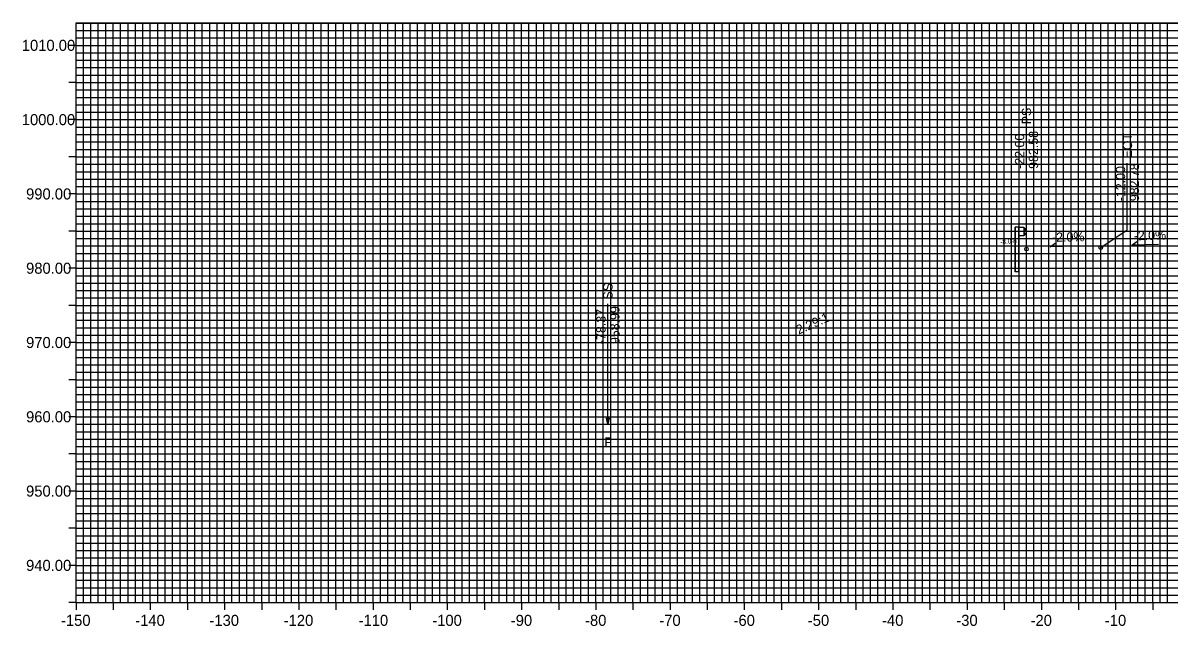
# Model space of a CAD drawing. Extents: x -157 to 157, y 932 to 1013.
# Drawn here: x -157.2 to -2.8, y 931.8 to 1013 of the extents above; entities that cross this region are included whole.
import ezdxf

# ---------------------------------------------------------------- set-up
doc = ezdxf.new("R2010")
doc.units = 0
for name, color, linetype in [('E_NCDOT_Terrain_Model_Breakline', 7, 'Continuous'), ('E_NCDOT_Terrain_Model_Contour_Imported', 7, 'Continuous'), ('E_NCDOT_Terrain_Model_Contour_Major', 7, 'Continuous'), ('E_NCDOT_Terrain_Model_Contour_Minor', 7, 'Continuous'), ('E_NCDOT_Terrain_Model_Flow_Arrows', 7, 'Continuous'), ('E_NCDOT_Terrain_Model_Hole', 7, 'Continuous'), ('E_NCDOT_Terrain_Model_Island', 7, 'Continuous'), ('E_NCDOT_Terrain_Model_Points_High', 7, 'Continuous'), ('E_NCDOT_Terrain_Model_Points_Low', 7, 'Continuous'), ('E_NCDOT_Terrain_Model_Triangles', 7, 'Continuous'), ('E_NCDOT_Vertical_Profile_Ground_Line', 7, 'Continuous'), ('P_HYD_Contour_Major', 7, 'Continuous'), ('P_HYD_Contour_Minor', 7, 'Continuous'), ('P_HYD_TC_Surface_Grass', 7, 'Continuous')]:
    doc.layers.add(name, color=color, linetype=linetype)

msp = doc.modelspace()

# ---------------------------------------------------------------- linework, layer by layer
at = {"layer": 'E_NCDOT_Terrain_Model_Breakline'}
for p, q in [((-150, 1013), (150, 1013)), ((-149, 935), (-149, 1013.02)), ((-148, 935), (-148, 1013.02)), ((-147, 935), (-147, 1013.02)), ((-146, 935), (-146, 1013.02)), ((-144, 935), (-144, 1013.02)), ((-143, 935), (-143, 1013.02)), ((-142, 935), (-142, 1013.02)), ((-141, 935), (-141, 1013.02)), ((-139, 935), (-139, 1013.02)), ((-138, 935), (-138, 1013.02)), ((-137, 935), (-137, 1013.02)), ((-136, 935), (-136, 1013.02)), ((-134, 935), (-134, 1013.02)), ((-133, 935), (-133, 1013.02)), ((-132, 935), (-132, 1013.02)), ((-131, 935), (-131, 1013.02)), ((-129, 935), (-129, 1013.02)), ((-128, 935), (-128, 1013.02)), ((-127, 935), (-127, 1013.02)), ((-126, 935), (-126, 1013.02)), ((-124, 935), (-124, 1013.02)), ((-123, 935), (-123, 1013.02)), ((-122, 935), (-122, 1013.02)), ((-121, 935), (-121, 1013.02)), ((-119, 935), (-119, 1013.02)), ((-118, 935), (-118, 1013.02)), ((-117, 935), (-117, 1013.02)), ((-116, 935), (-116, 1013.02)), ((-114, 935), (-114, 1013.02)), ((-113, 935), (-113, 1013.02)), ((-112, 935), (-112, 1013.02)), ((-111, 935), (-111, 1013.02)), ((-109, 935), (-109, 1013.02)), ((-108, 935), (-108, 1013.02)), ((-107, 935), (-107, 1013.02)), ((-106, 935), (-106, 1013.02)), ((-104, 935), (-104, 1013.02)), ((-103, 935), (-103, 1013.02)), ((-102, 935), (-102, 1013.02)), ((-101, 935), (-101, 1013.02)), ((-99, 935), (-99, 1013.02)), ((-98, 935), (-98, 1013.02)), ((-97, 935), (-97, 1013.02)), ((-96, 935), (-96, 1013.02)), ((-94, 935), (-94, 1013.02)), ((-93, 935), (-93, 1013.02)), ((-92, 935), (-92, 1013.02)), ((-91, 935), (-91, 1013.02)), ((-89, 935), (-89, 1013.02)), ((-88, 935), (-88, 1013.02)), ((-87, 935), (-87, 1013.02)), ((-86, 935), (-86, 1013.02)), ((-84, 935), (-84, 1013.02)), ((-83, 935), (-83, 1013.02)), ((-82, 935), (-82, 1013.02)), ((-81, 935), (-81, 1013.02)), ((-79, 935), (-79, 1013.02)), ((-78, 935), (-78, 1013.02)), ((-77, 935), (-77, 1013.02)), ((-76, 935), (-76, 1013.02)), ((-74, 935), (-74, 1013.02)), ((-73, 935), (-73, 1013.02)), ((-72, 935), (-72, 1013.02)), ((-71, 935), (-71, 1013.02)), ((-69, 935), (-69, 1013.02)), ((-68, 935), (-68, 1013.02)), ((-67, 935), (-67, 1013.02)), ((-66, 935), (-66, 1013.02)), ((-64, 935), (-64, 1013.02)), ((-63, 935), (-63, 1013.02)), ((-62, 935), (-62, 1013.02)), ((-61, 935), (-61, 1013.02)), ((-59, 935), (-59, 1013.02)), ((-58, 935), (-58, 1013.02)), ((-57, 935), (-57, 1013.02)), ((-56, 935), (-56, 1013.02)), ((-54, 935), (-54, 1013.02)), ((-53, 935), (-53, 1013.02)), ((-52, 935), (-52, 1013.02)), ((-51, 935), (-51, 1013.02)), ((-49, 935), (-49, 1013.02)), ((-48, 935), (-48, 1013.02)), ((-47, 935), (-47, 1013.02)), ((-46, 935), (-46, 1013.02)), ((-44, 935), (-44, 1013.02)), ((-43, 935), (-43, 1013.02)), ((-42, 935), (-42, 1013.02)), ((-41, 935), (-41, 1013.02)), ((-39, 935), (-39, 1013.02)), ((-38, 935), (-38, 1013.02)), ((-37, 935), (-37, 1013.02)), ((-36, 935), (-36, 1013.02)), ((-34, 935), (-34, 1013.02)), ((-33, 935), (-33, 1013.02)), ((-32, 935), (-32, 1013.02)), ((-31, 935), (-31, 1013.02)), ((-29, 935), (-29, 1013.02)), ((-28, 935), (-28, 1013.02)), ((-27, 935), (-27, 1013.02)), ((-26, 935), (-26, 1013.02)), ((-24, 935), (-24, 1013.02)), ((-23, 935), (-23, 1013.02)), ((-22, 935), (-22, 1013.02)), ((-21, 935), (-21, 1013.02)), ((-19, 935), (-19, 1013.02)), ((-18, 935), (-18, 1013.02)), ((-17, 935), (-17, 1013.02)), ((-16, 935), (-16, 1013.02)), ((-14, 935), (-14, 1013.02)), ((-13, 935), (-13, 1013.02)), ((-12, 935), (-12, 1013.02)), ((-11, 935), (-11, 1013.02)), ((-9, 935), (-9, 1013.02)), ((-8, 935), (-8, 1013.02)), ((-7, 935), (-7, 1013.02)), ((-6, 935), (-6, 1013.02)), ((-4, 935), (-4, 1013.02)), ((-3, 935), (-3, 1013.02)), ((-150, 1012), (150, 1012)), ((-150, 1011), (150, 1011)), ((-150, 1009), (150, 1009)), ((-150, 1008), (150, 1008)), ((-150, 1007), (150, 1007)), ((-150, 1006), (150, 1006)), ((-150, 1004), (150, 1004)), ((-150, 1003), (150, 1003)), ((-150, 1002), (150, 1002)), ((-150, 1001), (150, 1001)), ((-150, 999), (150, 999)), ((-150, 998), (150, 998)), ((-150, 997), (150, 997)), ((-150, 996), (150, 996)), ((-150, 994), (150, 994)), ((-150, 993), (150, 993)), ((-150, 992), (150, 992)), ((-150, 991), (150, 991)), ((-150, 989), (150, 989)), ((-150, 988), (150, 988)), ((-150, 987), (150, 987)), ((-150, 986), (150, 986)), ((-150, 984), (150, 984)), ((-150, 983), (150, 983)), ((-150, 982), (150, 982)), ((-150, 981), (150, 981)), ((-150, 979), (150, 979)), ((-150, 978), (150, 978)), ((-150, 977), (150, 977)), ((-150, 976), (150, 976)), ((-150, 974), (150, 974)), ((-150, 973), (150, 973)), ((-150, 972), (150, 972)), ((-150, 971), (150, 971)), ((-150, 969), (150, 969)), ((-150, 968), (150, 968)), ((-150, 967), (150, 967)), ((-150, 966), (150, 966)), ((-150, 964), (150, 964)), ((-150, 963), (150, 963)), ((-150, 962), (150, 962)), ((-150, 961), (150, 961)), ((-150, 959), (150, 959)), ((-150, 958), (150, 958)), ((-150, 957), (150, 957)), ((-150, 956), (150, 956)), ((-150, 954), (150, 954)), ((-150, 953), (150, 953)), ((-150, 952), (150, 952)), ((-150, 951), (150, 951)), ((-150, 949), (150, 949)), ((-150, 948), (150, 948)), ((-150, 947), (150, 947)), ((-150, 946), (150, 946)), ((-150, 944), (150, 944)), ((-150, 943), (150, 943)), ((-150, 942), (150, 942)), ((-150, 941), (150, 941)), ((-150, 939), (150, 939)), ((-150, 938), (150, 938)), ((-150, 937), (150, 937)), ((-150, 936), (150, 936))]:
    msp.add_line(p, q, dxfattribs=at)
at = {"layer": 'E_NCDOT_Terrain_Model_Contour_Imported'}
for p, q in [((-18.8, 982.88), (-18.12, 983.38)), ((-7.8, 983.1), (-7.12, 983.6)), ((-15.2, 982.96), (-18.8, 982.88)), ((-4.2, 983.18), (-7.8, 983.1))]:
    msp.add_line(p, q, dxfattribs=at)
at = {"layer": 'E_NCDOT_Terrain_Model_Contour_Minor'}
for p, q in [((-8.44, 985.17), (-8.44, 994.13)), ((-12, 982.78), (-8.44, 985.17))]:
    msp.add_line(p, q, dxfattribs=at)
at = {"layer": 'E_NCDOT_Terrain_Model_Hole'}
for p, q in [((-140, 935), (-140, 1013.02)), ((-130, 935), (-130, 1013.02)), ((-120, 935), (-120, 1013.02)), ((-110, 935), (-110, 1013.02)), ((-100, 935), (-100, 1013.02)), ((-90, 935), (-90, 1013.02)), ((-80, 935), (-80, 1013.02)), ((-70, 935), (-70, 1013.02)), ((-60, 935), (-60, 1013.02)), ((-50, 935), (-50, 1013.02)), ((-40, 935), (-40, 1013.02)), ((-30, 935), (-30, 1013.02)), ((-20, 935), (-20, 1013.02)), ((-10, 935), (-10, 1013.02)), ((-150, 1010), (150, 1010)), ((-150, 1000), (150, 1000)), ((-150, 990), (150, 990)), ((-150, 980), (150, 980)), ((-150, 970), (150, 970)), ((-150, 960), (150, 960)), ((-150, 950), (150, 950)), ((-150, 940), (150, 940))]:
    msp.add_line(p, q, dxfattribs=at)
at = {"layer": 'E_NCDOT_Terrain_Model_Points_High'}
for p, q in [((-145, 935), (-145, 1013.02)), ((-140, 935), (-140, 1013.02)), ((-135, 935), (-135, 1013.02)), ((-130, 935), (-130, 1013.02)), ((-125, 935), (-125, 1013.02)), ((-120, 935), (-120, 1013.02)), ((-115, 935), (-115, 1013.02)), ((-110, 935), (-110, 1013.02)), ((-105, 935), (-105, 1013.02)), ((-100, 935), (-100, 1013.02)), ((-95, 935), (-95, 1013.02)), ((-90, 935), (-90, 1013.02)), ((-85, 935), (-85, 1013.02)), ((-80, 935), (-80, 1013.02)), ((-75, 935), (-75, 1013.02)), ((-70, 935), (-70, 1013.02)), ((-65, 935), (-65, 1013.02)), ((-60, 935), (-60, 1013.02)), ((-55, 935), (-55, 1013.02)), ((-50, 935), (-50, 1013.02)), ((-45, 935), (-45, 1013.02)), ((-40, 935), (-40, 1013.02)), ((-35, 935), (-35, 1013.02)), ((-30, 935), (-30, 1013.02)), ((-25, 935), (-25, 1013.02)), ((-20, 935), (-20, 1013.02)), ((-15, 935), (-15, 1013.02)), ((-10, 935), (-10, 1013.02)), ((-5, 935), (-5, 1013.02)), ((-150, 1010), (-150.96, 1010)), ((-150, 1010), (150, 1010)), ((-150, 1005), (-150.96, 1005)), ((-150, 1005), (150, 1005)), ((-150, 1000), (-150.96, 1000)), ((-150, 1000), (150, 1000)), ((-150, 995), (-150.96, 995)), ((-150, 995), (150, 995)), ((-150, 990), (-150.96, 990)), ((-150, 990), (150, 990)), ((-150, 985), (-150.96, 985)), ((-150, 985), (150, 985)), ((-150, 980), (-150.96, 980)), ((-150, 980), (150, 980)), ((-150, 975), (-150.96, 975)), ((-150, 975), (150, 975)), ((-150, 970), (-150.96, 970)), ((-150, 970), (150, 970)), ((-150, 965), (-150.96, 965)), ((-150, 965), (150, 965)), ((-150, 960), (-150.96, 960)), ((-150, 960), (150, 960)), ((-150, 955), (-150.96, 955)), ((-150, 955), (150, 955)), ((-150, 950), (-150.96, 950)), ((-150, 950), (150, 950)), ((-150, 945), (-150.96, 945)), ((-150, 945), (150, 945)), ((-150, 940), (-150.96, 940)), ((-150, 940), (150, 940)), ((-150, 935), (-150.96, 935)), ((-150, 935), (-150, 934.04)), ((-145, 935), (-145, 934.04)), ((-140, 935), (-140, 934.04)), ((-135, 935), (-135, 934.04)), ((-130, 935), (-130, 934.04)), ((-125, 935), (-125, 934.04)), ((-120, 935), (-120, 934.04)), ((-115, 935), (-115, 934.04)), ((-110, 935), (-110, 934.04)), ((-105, 935), (-105, 934.04)), ((-100, 935), (-100, 934.04)), ((-95, 935), (-95, 934.04)), ((-90, 935), (-90, 934.04)), ((-85, 935), (-85, 934.04)), ((-80, 935), (-80, 934.04)), ((-75, 935), (-75, 934.04)), ((-70, 935), (-70, 934.04)), ((-65, 935), (-65, 934.04)), ((-60, 935), (-60, 934.04)), ((-55, 935), (-55, 934.04)), ((-50, 935), (-50, 934.04)), ((-45, 935), (-45, 934.04)), ((-40, 935), (-40, 934.04)), ((-35, 935), (-35, 934.04)), ((-30, 935), (-30, 934.04)), ((-25, 935), (-25, 934.04)), ((-20, 935), (-20, 934.04)), ((-15, 935), (-15, 934.04)), ((-10, 935), (-10, 934.04)), ((-5, 935), (-5, 934.04))]:
    msp.add_line(p, q, dxfattribs=at)
at = {"layer": 'E_NCDOT_Terrain_Model_Points_Low'}
for p, q in [((-150, 1013.02), (150, 1013.02)), ((-150, 935), (-150, 1013.02)), ((-150, 935), (150, 935))]:
    msp.add_line(p, q, dxfattribs=at)
at = {"layer": 'E_NCDOT_Vertical_Profile_Ground_Line'}
for p, q in [((-22, 982.58), (-22, 998.18)), ((-78.37, 958.99), (-78.37, 975.19))]:
    msp.add_line(p, q, dxfattribs=at)
msp.add_lwpolyline([(-78.37, 958.99), (-78.55, 959.81), (-78.2, 959.81)], close=True, dxfattribs=at)
for centre in [(-22, 982.58), (-12, 982.78)]:
    msp.add_circle(centre, 0.24, dxfattribs=at)
at = {"layer": 'P_HYD_TC_Surface_Grass'}
for p, q in [((-23.03, 985.52), (-23.53, 985.52)), ((-23.53, 985.52), (-23.51, 985.52)), ((-23.53, 979.52), (-23.53, 985.52)), ((-23.51, 985.52), (-23.51, 979.52)), ((-23.04, 985.52), (-23.03, 985.52)), ((-23.04, 979.52), (-23.04, 985.52)), ((-23.03, 985.52), (-22.36, 985.52)), ((-23.03, 985.52), (-23.03, 979.52)), ((-22.36, 985.52), (-22.36, 984.35)), ((-22.36, 985.44), (-22.27, 985.42)), ((-22.36, 984.98), (-22.36, 984.93)), ((-22.36, 984.93), (-22.36, 984.88)), ((-22.12, 985.19), (-22.33, 985.05)), ((-22.33, 984.82), (-22.12, 984.68)), ((-22.26, 985.41), (-22.12, 985.32)), ((-22.36, 984.35), (-23.03, 984.35)), ((-22.27, 984.44), (-22.36, 984.43)), ((-22.12, 984.55), (-22.26, 984.45)), ((-23.03, 979.52), (-23.53, 979.52)), ((-23.51, 979.52), (-23.53, 979.52)), ((-23.03, 979.52), (-23.04, 979.52))]:
    msp.add_line(p, q, dxfattribs=at)
for centre, radius, start, end in [((-22.28, 984.98), 0.0787, 124.6522, 179.98), ((-22.28, 984.88), 0.0787, 180.02, 235.3478), ((-22.27, 985.39), 0.0328, 54.7024, 80), ((-22.16, 985.25), 0.0787, 304.6522, 54.7024), ((-22.27, 984.48), 0.0328, 280, 305.2976), ((-22.16, 984.61), 0.0787, 305.2976, 55.3478)]:
    msp.add_arc(centre, radius, start, end, dxfattribs=at)

# ---------------------------------------------------------------- texts
at = {"layer": 'E_NCDOT_Terrain_Model_Contour_Major'}
for s, p in [('SS', (-77.75, 975.79)), ('-78.37', (-78.69, 969.79)), ('958.99', (-76.81, 969.79))]:
    msp.add_text(s, height=1.248, rotation=90, dxfattribs=at).set_placement(p)
msp.add_text('F', height=1.25, dxfattribs=at).set_placement((-78.85, 955.97))
at = {"layer": 'E_NCDOT_Terrain_Model_Flow_Arrows'}
msp.add_text('-8.0%', height=0.624, rotation=4.5739, dxfattribs=at).set_placement((-25.51, 983.23))
at = {"layer": 'E_NCDOT_Terrain_Model_Island'}
for s, p in [('1010.00', (-157.31, 1009.26)), ('1000.00', (-157.31, 999.26)), ('990.00', (-156.73, 989.26)), ('980.00', (-156.73, 979.26)), ('970.00', (-156.73, 969.26)), ('960.00', (-156.73, 959.26)), ('950.00', (-156.73, 949.26)), ('940.00', (-156.73, 939.26)), ('-150', (-152.03, 931.86)), ('-140', (-142.03, 931.86)), ('-130', (-132.03, 931.86)), ('-120', (-122.03, 931.86)), ('-110', (-111.95, 931.86)), ('-100', (-102.03, 931.86)), ('-90', (-91.45, 931.86)), ('-80', (-81.45, 931.86)), ('-70', (-71.45, 931.86)), ('-60', (-61.45, 931.86)), ('-50', (-51.45, 931.86)), ('-40', (-41.45, 931.86)), ('-30', (-31.45, 931.86)), ('-20', (-21.45, 931.86)), ('-10', (-11.45, 931.86))]:
    msp.add_text(s, height=1.488, dxfattribs=at).set_placement(p)
at = {"layer": 'E_NCDOT_Terrain_Model_Triangles'}
for s, p in [('PS', (-21.38, 999.38)), ('-22.00', (-22.31, 993.38)), ('982.58', (-20.44, 993.38)), ('EOT', (-7.78, 994.78)), ('-12.00', (-8.71, 989.02)), ('982.78', (-6.84, 989.02))]:
    msp.add_text(s, height=1.248, rotation=90, dxfattribs=at).set_placement(p)
at = {"layer": 'P_HYD_Contour_Major'}
msp.add_text('-2.0%', height=1.248, rotation=1.1458, dxfattribs=at).set_placement((-7.55, 983.76))
at = {"layer": 'P_HYD_Contour_Minor'}
for s, rotation, p in [('-2.0%', 1.1458, (-18.55, 983.54)), ('2.29:1', 23.6294, (-52.69, 971.06))]:
    msp.add_text(s, height=1.248, rotation=rotation, dxfattribs=at).set_placement(p)

doc.saveas('drawing.dxf')
